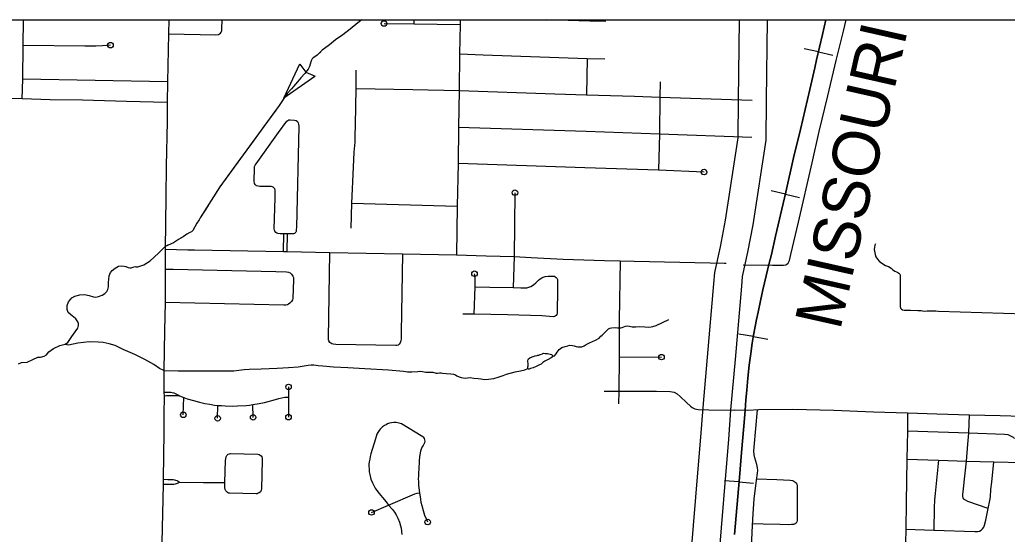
# Model space of a CAD drawing. Extents: x 670147 to 673275, y 705573 to 707613.
# Drawn here: x 671751.4 to 671930, y 706596.3 to 706689.4 of the extents above; entities that cross this region are included whole.
import ezdxf

# ---------------------------------------------------------------- set-up
doc = ezdxf.new("R2010")
doc.units = 0
for name, color, linetype in [('15', 7, 'Continuous'), ('33', 7, 'Continuous'), ('35', 7, 'Continuous'), ('40', 7, 'Continuous'), ('43', 7, 'Continuous'), ('R_NoPlot', 7, 'Continuous')]:
    doc.layers.add(name, color=color, linetype=linetype)

msp = doc.modelspace()

# ---------------------------------------------------------------- linework, layer by layer
at = {"layer": '15'}
for points in [[(671881.3, 706668.03), (671881.36, 706674.84), (671881.54, 706689.36)], [(671886.54, 706689.36), (671886.36, 706674.78), (671886.29, 706667.62)], [(671872.81, 706592.8), (671874.09, 706608.19), (671874.56, 706613.87), (671874.96, 706619.24), (671875.76, 706628.34), (671876.92, 706641.62), (671877.08, 706643.69), (671878.11, 706648.33), (671879.02, 706653.1), (671881.3, 706668.03)], [(671886.29, 706667.62), (671883.94, 706652.26), (671883.01, 706647.33), (671882.04, 706642.95), (671881.9, 706641.2), (671880.74, 706627.91), (671879.95, 706618.84), (671879.55, 706613.48), (671879.07, 706607.77), (671877.8, 706592.39)]]:
    msp.add_lwpolyline(points, dxfattribs=at)
at = {"layer": '33'}
for points in [[(671751.86, 706675.07), (671751.98, 706678.6), (671752.06, 706684.72), (671752.09, 706689.36)], [(671778.36, 706689.36), (671778.33, 706686.82), (671778.17, 706678.14), (671778.08, 706674.37), (671778.07, 706670.98), (671777.92, 706662.91), (671777.87, 706657.34), (671777.71, 706647.9), (671777.75, 706644.28), (671777.75, 706638.26), (671777.62, 706633.11), (671777.5, 706625.93), (671777.5, 706622.05), (671777.52, 706621.31), (671777.51, 706618.04), (671777.5, 706614.82), (671777.35, 706606.28), (671777.33, 706605.34), (671777.13, 706594.83)], [(671778.33, 706686.82), (671786.91, 706686.62), (671787.39, 706686.71), (671787.73, 706686.93), (671787.87, 706687.1), (671787.96, 706687.36), (671787.99, 706687.7), (671788.02, 706689.36)], [(671822.75, 706688.63), (671822.75, 706689.36)], [(671831.07, 706689.36), (671831.05, 706688.5), (671830.96, 706683.18), (671830.85, 706676.58), (671830.76, 706669.95), (671830.67, 706663.36), (671830.54, 706655.67), (671830.38, 706646.87)], [(671857.37, 706689.02), (671854.48, 706689.1), (671846.6, 706689.36)], [(671854.48, 706689.36), (671854.48, 706689.1)], [(671900.33, 706687.31), (671900.81, 706689.36)], [(671817.29, 706688.68), (671822.75, 706688.63), (671831.05, 706688.5)], [(671882.21, 706645.06), (671887.52, 706644.99), (671888.93, 706644.98), (671889.53, 706644.99), (671889.95, 706645.05), (671890.13, 706645.15), (671890.33, 706645.38), (671890.58, 706645.84), (671890.84, 706646.92), (671892.21, 706652.75), (671894.68, 706663.47), (671895.97, 706669.16), (671897.51, 706675.62), (671899.01, 706682.02), (671900.33, 706687.31)], [(671767.84, 706684.76), (671766.41, 706684.65), (671765.2, 706684.56), (671764.45, 706684.56), (671763.21, 706684.56), (671752.06, 706684.72)], [(671830.96, 706683.18), (671835.21, 706683.04), (671854.01, 706682.37), (671857.23, 706682.31)], [(671854.01, 706682.37), (671853.87, 706675.77)], [(671811.33, 706651.66), (671811.49, 706656.18), (671811.75, 706662.71), (671811.92, 706665.41), (671812.05, 706667.22), (671812.06, 706668.37), (671812.14, 706670.37), (671812.25, 706676.92), (671812.26, 706680.25)], [(671778.17, 706678.14), (671751.98, 706678.6)], [(671812.25, 706676.92), (671822.48, 706676.77), (671830.85, 706676.58)], [(671830.85, 706676.58), (671848.19, 706675.98), (671853.87, 706675.77), (671862.56, 706675.52), (671867.16, 706675.36), (671883.86, 706674.81)], [(671867.19, 706678.14), (671867.16, 706675.36), (671867.08, 706668.76), (671866.89, 706662.14)], [(671778.08, 706674.37), (671770.72, 706674.56), (671762.79, 706674.81), (671756.96, 706674.9), (671751.86, 706675.07), (671747.69, 706675.11), (671746.42, 706675.14), (671742.28, 706675.22), (671733.94, 706675.42), (671725.56, 706675.57), (671722.68, 706675.63), (671718.93, 706675.66), (671714.77, 706675.79), (671699.06, 706676.14)], [(671799.85, 706650.63), (671799.16, 706650.65), (671798.5, 706650.68), (671798.08, 706650.71), (671797.91, 706650.79), (671797.73, 706650.91), (671797.55, 706651.12), (671797.46, 706651.32), (671797.45, 706651.56), (671797.6, 706657.18), (671797.6, 706658.53), (671797.53, 706658.77), (671797.38, 706658.97), (671797.26, 706659.07), (671797.13, 706659.13), (671796.9, 706659.2), (671794.81, 706659.23), (671794.51, 706659.25), (671794.25, 706659.35), (671794.06, 706659.52), (671793.88, 706659.73), (671793.85, 706659.87), (671793.83, 706660.12), (671793.86, 706662.58), (671793.89, 706662.83), (671793.98, 706663.07), (671794.18, 706663.33), (671798.22, 706668.99), (671799.71, 706671), (671799.9, 706671.17), (671800.07, 706671.24), (671800.29, 706671.25), (671801.1, 706671.21), (671801.38, 706671.17), (671801.63, 706670.97), (671801.78, 706670.74), (671801.85, 706670.5), (671801.87, 706670.07), (671801.46, 706651.87), (671801.43, 706651.41), (671801.4, 706651.09), (671801.32, 706650.94), (671801.22, 706650.83), (671801.08, 706650.74), (671800.92, 706650.68), (671800.69, 706650.64), (671800.29, 706650.63), (671799.85, 706650.63)], [(671830.76, 706669.95), (671853.83, 706669.19), (671867.08, 706668.76), (671883.8, 706668.16)], [(671875.14, 706661.82), (671866.89, 706662.14), (671853.6, 706662.61), (671830.67, 706663.36)], [(671840.95, 706658.09), (671840.81, 706646.55)], [(671811.49, 706656.18), (671830.54, 706655.67)], [(671799.09, 706647.46), (671799.16, 706650.65)], [(671799.76, 706647.46), (671799.85, 706650.63)], [(671777.71, 706647.9), (671781.81, 706647.78), (671783.01, 706647.74), (671799.09, 706647.46), (671799.76, 706647.46), (671807.52, 706647.3), (671820.6, 706647.07), (671830.38, 706646.87), (671835.78, 706646.7), (671840.81, 706646.55), (671843.88, 706646.4), (671849.66, 706646.09), (671857.12, 706645.83), (671860, 706645.78), (671862.52, 706645.72), (671876.27, 706645.44), (671878.87, 706645.34), (671879.12, 706645.33)], [(671906.17, 706648.85), (671906.02, 706648.63), (671905.93, 706648.24), (671905.92, 706647.83), (671906.07, 706646.95), (671906.23, 706646.47), (671906.48, 706646.08), (671906.8, 706645.69), (671907.3, 706645.33), (671907.96, 706644.96), (671908.52, 706644.73), (671908.97, 706644.46), (671909.22, 706644.22), (671909.62, 706643.89), (671909.92, 706643.76), (671910.18, 706643.68), (671910.34, 706643.56), (671910.53, 706643.39), (671910.61, 706643.25), (671910.6, 706642.91), (671910.62, 706641.62), (671910.62, 706639.54), (671910.6, 706637.55), (671910.69, 706637.23), (671910.83, 706637.03), (671911.03, 706636.92), (671911.3, 706636.86), (671911.58, 706636.85), (671912.44, 706636.86), (671913.78, 706636.82), (671914.39, 706636.79), (671914.65, 706636.74), (671915, 706636.7), (671915.48, 706636.74), (671916.17, 706636.74), (671917.03, 706636.74), (671917.52, 706636.7), (671933.17, 706636.2)], [(671820.6, 706647.07), (671820.38, 706632.84), (671820.38, 706631.67), (671820.35, 706631.34), (671820.29, 706631.13), (671820.19, 706630.93), (671820.04, 706630.72), (671819.82, 706630.55), (671819.62, 706630.48), (671819.4, 706630.48), (671808.55, 706630.66), (671808.11, 706630.7), (671807.86, 706630.75), (671807.67, 706630.87), (671807.5, 706631.03), (671807.34, 706631.3), (671807.27, 706631.48), (671807.23, 706631.76), (671807.52, 706647.3)], [(671840.81, 706646.55), (671840.64, 706640.98)], [(671777.75, 706644.28), (671779.17, 706644.29), (671797.72, 706643.83), (671799.67, 706643.79), (671799.99, 706643.73), (671800.3, 706643.58), (671800.56, 706643.38), (671800.7, 706643.21), (671800.83, 706642.98), (671800.9, 706642.76), (671800.92, 706642.4), (671800.8, 706638.98), (671800.74, 706638.72), (671800.57, 706638.41), (671800.27, 706638.11), (671800.01, 706637.92), (671799.83, 706637.84), (671799.56, 706637.79), (671799.17, 706637.79), (671777.75, 706638.26)], [(671860, 706645.78), (671859.8, 706635.04)], [(671833.57, 706636.11), (671833.74, 706641.06), (671833.76, 706642.44), (671833.74, 706642.94), (671833.65, 706643.44)], [(671840.64, 706640.98), (671842.05, 706640.92), (671842.9, 706640.91), (671843.1, 706640.92), (671843.44, 706640.99), (671843.82, 706641.12), (671844.33, 706641.43), (671844.75, 706641.78), (671845.2, 706642.27), (671845.53, 706642.52), (671845.8, 706642.7), (671846.05, 706642.81), (671846.42, 706642.93), (671846.96, 706642.99), (671847.55, 706643.02), (671847.95, 706643.01), (671848.12, 706642.98), (671848.25, 706642.91), (671848.4, 706642.78), (671848.5, 706642.64), (671848.58, 706642.53), (671848.63, 706642.39), (671848.67, 706640.18), (671848.61, 706636.85), (671848.6, 706636.32), (671848.52, 706636.07), (671848.38, 706635.89), (671848.23, 706635.77), (671848.09, 706635.7), (671847.93, 706635.68), (671845.79, 706635.81), (671839.59, 706635.99)], [(671833.74, 706641.06), (671836.39, 706640.99), (671840.64, 706640.98)], [(671839.59, 706635.99), (671833.57, 706636.11), (671831.53, 706636.16)], [(671859.8, 706635.04), (671859.8, 706628.45), (671859.73, 706622.24), (671859.65, 706619.94)], [(671859.8, 706628.45), (671867.45, 706628.37)], [(671800.03, 706622.98), (671800, 706621.11), (671800.01, 706617.51)], [(671777.5, 706622.05), (671777.99, 706622.03), (671778.49, 706622.02), (671778.77, 706622.01), (671778.97, 706621.98), (671779.26, 706621.89), (671779.66, 706621.71), (671780, 706621.55), (671780.31, 706621.36), (671779.95, 706621.35), (671779.43, 706621.37), (671778.6, 706621.39), (671777.97, 706621.36), (671777.52, 706621.31)], [(671780.31, 706621.36), (671781.11, 706621.04), (671781.7, 706620.84), (671782.82, 706620.5), (671783.92, 706620.22), (671784.91, 706619.99), (671785.78, 706619.84), (671786.62, 706619.71), (671787.27, 706619.63), (671787.88, 706619.6), (671788.54, 706619.56), (671789.81, 706619.51), (671790.77, 706619.54), (671792.36, 706619.65), (671792.95, 706619.71), (671793.59, 706619.8), (671794.7, 706619.97), (671795.66, 706620.16), (671796.33, 706620.32), (671797.23, 706620.58), (671798.26, 706620.91), (671798.84, 706621.02), (671799.35, 706621.1), (671800, 706621.11)], [(671857.08, 706622.21), (671859.73, 706622.24), (671866.56, 706622.2), (671869, 706622.13), (671869.75, 706622.02), (671870.27, 706621.76), (671870.84, 706621.27), (671871.98, 706620.17), (671872.71, 706619.48), (671873.02, 706619.24), (671873.46, 706619.02), (671874.09, 706618.89), (671876.03, 706618.83), (671880.7, 706618.78)], [(671781, 706617.94), (671781.11, 706621.04)], [(671787.21, 706617.31), (671787.27, 706619.63)], [(671793.62, 706617.48), (671793.59, 706619.8)], [(671911.93, 706618.24), (671905.78, 706618.4), (671898.59, 706618.72), (671891.21, 706618.9), (671885.06, 706618.86), (671883.04, 706618.73), (671880.7, 706618.78)], [(671882.19, 706591.77), (671883.16, 706592.34), (671883.7, 706594), (671883.89, 706597.95), (671884.05, 706600.02), (671884.23, 706602.76), (671884.61, 706606.04), (671884.8, 706607.37), (671884.86, 706607.88), (671884.82, 706608.36), (671884.68, 706608.93), (671884.48, 706609.56), (671884.32, 706610.15), (671884.2, 706610.7), (671884.16, 706611.34), (671884.23, 706612.07), (671884.83, 706618.85)], [(671911.93, 706618.24), (671911.9, 706614.98), (671911.79, 706609.9), (671911.66, 706602.1), (671911.64, 706597.24), (671911.56, 706594.75)], [(671932.61, 706617.66), (671928.68, 706617.78), (671923.12, 706617.9), (671917.23, 706618.04), (671913.71, 706618.17), (671911.93, 706618.24)], [(671926.53, 706600.99), (671922.82, 706602.27), (671922.39, 706602.5), (671922.2, 706602.63), (671922.1, 706602.78), (671921.97, 706602.95), (671921.92, 706603.15), (671921.92, 706603.52), (671922.02, 706604.53), (671922.22, 706606.33), (671922.58, 706609.56), (671922.82, 706612.61), (671923.02, 706614.61), (671923.07, 706616.35), (671923.12, 706617.9)], [(671825.18, 706598.55), (671824.97, 706599.1), (671824.69, 706599.76), (671824.42, 706600.57), (671824.17, 706601.46), (671824.03, 706602.08), (671823.93, 706602.7), (671823.75, 706603.83), (671823.65, 706604.75), (671823.61, 706605.18), (671823.58, 706605.89), (671823.55, 706606.35), (671823.58, 706606.85), (671823.59, 706607.51), (671823.64, 706608.1), (671823.73, 706609.58), (671823.78, 706610.38), (671823.87, 706611.02), (671823.97, 706611.44), (671824.13, 706611.95), (671824.39, 706612.34), (671824.56, 706612.68), (671824.66, 706612.93), (671824.71, 706613.2), (671824.69, 706613.4), (671824.61, 706613.63), (671824.46, 706613.81), (671824.31, 706613.96), (671824.02, 706614.16), (671820.43, 706616.31), (671820, 706616.44), (671819.46, 706616.55), (671819.09, 706616.55), (671818.66, 706616.51), (671818.27, 706616.43), (671817.94, 706616.29), (671817.65, 706616.14), (671817.38, 706615.99), (671817.01, 706615.75), (671816.85, 706615.6), (671816.58, 706615.33), (671816.39, 706615.08), (671816.19, 706614.77), (671816, 706614.42), (671815.74, 706613.6), (671814.9, 706610.86), (671814.8, 706610.38), (671814.7, 706609.92), (671814.62, 706609.45), (671814.57, 706608.99), (671814.57, 706608.67), (671814.58, 706608.16), (671814.61, 706607.62), (671814.71, 706607.16), (671814.93, 706606.31), (671815.18, 706605.64), (671815.42, 706605.15), (671815.71, 706604.67), (671816.01, 706604.24), (671816.41, 706603.72), (671817.01, 706603.01), (671817.66, 706602.21), (671818.1, 706601.6), (671818.8, 706600.82), (671819.17, 706600.31), (671819.47, 706599.86), (671819.79, 706599.24), (671820.09, 706598.53), (671820.29, 706597.85), (671820.39, 706597.44), (671820.52, 706596.29)], [(671931.25, 706613.68), (671931.06, 706613.81), (671930.63, 706614.09), (671930.11, 706614.3), (671929.46, 706614.41), (671923.02, 706614.61), (671911.9, 706614.98)], [(671788.51, 706605.68), (671788.64, 706609.68), (671788.72, 706610.36), (671788.86, 706610.6), (671789.12, 706610.83), (671789.34, 706610.9), (671789.55, 706610.94), (671794.45, 706610.84), (671794.69, 706610.79), (671794.92, 706610.65), (671795.07, 706610.5), (671795.19, 706610.32), (671795.25, 706610.07), (671795.27, 706609.76), (671795.14, 706604.55), (671795.08, 706604.3), (671794.93, 706604.04), (671794.69, 706603.84), (671794.55, 706603.75), (671794.38, 706603.68), (671794.2, 706603.66), (671789.34, 706603.79), (671789.16, 706603.8), (671788.98, 706603.88), (671788.86, 706603.99), (671788.71, 706604.18), (671788.58, 706604.41), (671788.53, 706604.75), (671788.5, 706605.16), (671788.51, 706605.68)], [(671911.64, 706597.24), (671916.69, 706597.09), (671924.08, 706596.82), (671924.64, 706596.84), (671924.97, 706596.93), (671925.26, 706597.11), (671925.51, 706597.35), (671925.71, 706597.63), (671925.84, 706597.97), (671926.08, 706598.88), (671926.53, 706600.99), (671926.84, 706602.43), (671926.92, 706603.14), (671927.01, 706604.43), (671927.19, 706605.78), (671927.54, 706609.44)], [(671911.79, 706609.9), (671917.5, 706609.75), (671922.58, 706609.56), (671927.54, 706609.44), (671932.76, 706609.29)], [(671917.5, 706609.75), (671916.93, 706603.69), (671916.83, 706602.57), (671916.75, 706601.13), (671916.69, 706597.09)], [(671777.35, 706606.28), (671778.21, 706606.26), (671779.14, 706606.25), (671779.43, 706606.2), (671779.59, 706606.14), (671779.82, 706606.05), (671780.06, 706605.94), (671780.23, 706605.83), (671780.33, 706605.77), (671780.24, 706605.73), (671780.07, 706605.61), (671779.74, 706605.44), (671779.55, 706605.39), (671779.31, 706605.37), (671778.55, 706605.34), (671777.33, 706605.34)], [(671780.33, 706605.77), (671784.67, 706605.68), (671788.51, 706605.68)], [(671884.64, 706606.35), (671888.33, 706606.27), (671890.72, 706606.14), (671891.12, 706606.04), (671891.4, 706605.92), (671891.57, 706605.8), (671891.75, 706605.66), (671891.92, 706605.41), (671891.97, 706605.26), (671892, 706604.97), (671892, 706599.05), (671891.98, 706598.82), (671891.93, 706598.57), (671891.79, 706598.38), (671891.63, 706598.24), (671891.47, 706598.15), (671891.31, 706598.11), (671890.94, 706598.08), (671890.46, 706598.07), (671888.92, 706598.08), (671885.81, 706598.15), (671883.91, 706598.23)], [(671815.02, 706600.29), (671818.1, 706601.6), (671822.84, 706603.63), (671823.27, 706603.78), (671823.75, 706603.83)]]:
    msp.add_lwpolyline(points, dxfattribs=at)
for centre in [(671817.29, 706688.68), (671767.84, 706684.76), (671875.14, 706661.82), (671840.95, 706658.09), (671833.65, 706643.44), (671867.45, 706628.37), (671800.03, 706622.98), (671781, 706617.94), (671787.21, 706617.31), (671793.62, 706617.48), (671800.01, 706617.51), (671815.02, 706600.29), (671825.18, 706598.55)]:
    msp.add_circle(centre, 0.5, dxfattribs=at)
at = {"layer": '35'}
for points in [[(671751.22, 706627.13), (671751.77, 706627.37), (671752.76, 706627.48), (671753.78, 706627.93), (671754.69, 706628.38), (671755.2, 706628.38), (671755.87, 706628.55), (671756.24, 706628.8), (671756.72, 706629.31), (671757.51, 706629.91), (671758.7, 706630.47), (671759.65, 706630.72), (671760.13, 706631.04), (671760.82, 706632.08), (671761.44, 706632.96), (671761.95, 706633.61), (671762.06, 706634.09), (671762.05, 706634.43), (671761.94, 706634.74), (671761.58, 706635.29), (671761.12, 706635.65), (671760.96, 706635.76), (671760.2, 706636.43), (671760.03, 706637), (671760.03, 706637.71), (671760.22, 706638.36), (671760.86, 706639.06), (671761.41, 706639.38), (671762.28, 706639.63), (671763.16, 706639.69), (671763.97, 706639.5), (671764.75, 706639.27), (671765.17, 706639.21), (671765.68, 706639.33), (671766.34, 706639.55), (671766.8, 706639.88), (671767.16, 706640.22), (671767.36, 706640.61), (671767.46, 706641.08), (671767.45, 706641.86), (671767.54, 706642.45), (671767.59, 706643.07), (671767.84, 706643.68), (671768.11, 706644.03), (671768.69, 706644.46), (671769.31, 706644.79), (671769.86, 706644.88), (671770.29, 706644.84), (671770.64, 706644.73), (671771.03, 706644.56), (671771.31, 706644.5), (671771.56, 706644.5), (671771.92, 706644.64), (671772.26, 706644.74), (671772.4, 706644.72), (671772.76, 706644.69), (671773.86, 706645.04), (671774.98, 706645.78), (671776.52, 706647.17), (671777.71, 706648.38)], [(671847.83, 706628.52), (671848.13, 706628.63), (671848.4, 706628.94), (671848.6, 706629.28), (671848.96, 706629.74), (671849.45, 706630.1), (671850.02, 706630.3), (671850.52, 706630.43), (671850.83, 706630.5), (671851.34, 706630.46), (671851.64, 706630.38), (671852, 706630.3), (671852.32, 706630.21), (671852.67, 706630.21), (671853.04, 706630.25), (671853.46, 706630.41), (671853.82, 706630.63), (671854.46, 706630.96), (671855.51, 706631.43), (671856.18, 706631.82), (671856.51, 706632.17), (671856.71, 706632.35), (671856.95, 706632.58), (671857.3, 706632.92), (671857.88, 706633.49), (671858.11, 706633.6), (671858.42, 706633.69), (671859.18, 706633.73), (671859.51, 706633.68), (671859.8, 706633.66), (671860.08, 706633.68), (671860.35, 706633.75), (671860.95, 706633.97), (671861.33, 706634), (671861.65, 706633.98), (671862.13, 706633.84), (671862.81, 706633.85), (671863.49, 706633.9), (671864.44, 706633.86), (671865.18, 706633.81), (671865.56, 706633.85), (671865.91, 706633.9), (671866.46, 706634.08), (671868.76, 706635.16)], [(671777.5, 706625.93), (671776.71, 706626.31), (671775.66, 706627.06), (671774.05, 706627.92), (671772.21, 706628.86), (671770.1, 706629.77), (671768.67, 706630.44), (671767.58, 706630.78), (671766.49, 706631.01), (671765.59, 706631.08), (671763.98, 706631.16), (671761.95, 706630.89), (671760.26, 706630.55), (671759.99, 706630.59), (671759.65, 706630.72)], [(671845.83, 706627.22), (671845.7, 706627.12), (671845.4, 706626.99), (671844.78, 706626.67), (671844.25, 706626.46), (671843.78, 706626.33), (671843.5, 706626.2), (671843.4, 706626.2), (671843.3, 706626.25), (671843.26, 706626.32), (671843.27, 706626.51), (671843.29, 706626.62), (671843.34, 706626.77), (671843.33, 706627.09), (671843.29, 706627.72), (671843.33, 706627.91), (671843.42, 706628.08), (671843.66, 706628.25), (671844.07, 706628.43), (671844.59, 706628.59)], [(671844.59, 706628.59), (671844.97, 706628.68), (671845.11, 706628.72), (671845.29, 706628.73), (671845.53, 706628.85), (671845.91, 706628.98), (671846.01, 706629.05), (671846.14, 706629.07), (671846.43, 706629.04), (671846.85, 706629.01), (671847.33, 706628.93), (671847.59, 706628.82), (671847.7, 706628.73), (671847.8, 706628.63), (671847.83, 706628.58), (671847.83, 706628.52), (671847.76, 706628.42), (671847.51, 706628.27), (671846.94, 706627.93), (671846.39, 706627.63), (671846, 706627.38), (671845.83, 706627.22)], [(671777.5, 706625.93), (671780.07, 706625.89), (671783.02, 706625.91), (671789.29, 706625.92), (671790.12, 706625.88), (671791.05, 706626.01), (671791.99, 706626.13), (671792.89, 706626.2), (671795.07, 706626.24), (671797.95, 706626.37), (671799.99, 706626.47), (671801.75, 706626.6), (671802.88, 706626.79), (671803.59, 706626.92), (671804.11, 706626.95), (671804.57, 706626.95), (671805, 706626.93), (671805.37, 706626.87), (671806.24, 706626.82), (671808.14, 706626.64), (671810.72, 706626.52), (671813.8, 706626.34), (671818.09, 706626.08), (671820.78, 706625.85), (671821.55, 706625.72), (671822.3, 706625.72), (671823.39, 706625.77), (671823.95, 706625.8), (671824.87, 706625.67), (671825.46, 706625.67), (671826.12, 706625.62), (671826.69, 706625.48), (671826.96, 706625.45), (671827.31, 706625.52), (671827.59, 706625.53), (671827.84, 706625.48), (671828.54, 706625.4), (671829.34, 706625.35), (671829.83, 706625.27), (671830.21, 706625.17), (671830.45, 706625), (671830.85, 706624.78), (671831.26, 706624.67), (671831.61, 706624.62), (671831.96, 706624.58), (671832.37, 706624.62), (671832.84, 706624.67), (671833.54, 706624.57), (671834.29, 706624.48), (671834.79, 706624.42), (671835.51, 706624.35), (671836.18, 706624.37), (671837.11, 706624.5), (671837.9, 706624.72), (671838.85, 706625.07), (671839.43, 706625.27), (671840.99, 706625.72), (671841.94, 706625.89), (671842.72, 706626.07), (671843.26, 706626.32)]]:
    msp.add_lwpolyline(points, dxfattribs=at)
at = {"layer": '40'}
for p, q in [((671895.83, 706683.53), (671893.26, 706684.13)), ((671895.83, 706683.53), (671898.4, 706682.93)), ((671889.84, 706657.82), (671887.26, 706658.41)), ((671889.84, 706657.82), (671892.41, 706657.23)), ((671884.06, 706632.07), (671881.45, 706632.49)), ((671884.06, 706632.07), (671886.66, 706631.64)), ((671881.46, 706605.8), (671878.83, 706606.02)), ((671881.46, 706605.8), (671884.09, 706605.58))]:
    msp.add_line(p, q, dxfattribs=at)
for points in [[(671897.19, 706689.36), (671896.56, 706686.69), (671895.5, 706682.11), (671895.17, 706680.64), (671894.26, 706676.76), (671893.41, 706673.14), (671892.61, 706669.5), (671891.33, 706664.4), (671889.92, 706658.2), (671889.46, 706656.17), (671888.06, 706650.21), (671887.31, 706646.95), (671886.87, 706645.11), (671886.4, 706643.07), (671885.8, 706640.52), (671885.35, 706638.52), (671884.9, 706636.5), (671884.64, 706635.2), (671884.39, 706633.88), (671884.1, 706632.33), (671883.87, 706630.92), (671883.6, 706629.04), (671883.3, 706626.89), (671883.04, 706624.57), (671882.85, 706622.37), (671882.7, 706620.65), (671882.57, 706618.71), (671882.31, 706615.89), (671881.9, 706611.15), (671881.53, 706606.63), (671880.66, 706596.28)], [(671885.8, 706640.52), (671886.4, 706643.07), (671886.87, 706645.11), (671887.31, 706646.95), (671888.06, 706650.21), (671889.46, 706656.17), (671889.92, 706658.2), (671891.33, 706664.4), (671892.61, 706669.5), (671893.41, 706673.14), (671894.26, 706676.76), (671895.17, 706680.64), (671895.5, 706682.11), (671896.56, 706686.69), (671897.19, 706689.36)], [(671897.19, 706689.36), (671896.56, 706686.69), (671895.5, 706682.11), (671895.17, 706680.64), (671894.26, 706676.76), (671893.41, 706673.14), (671892.61, 706669.5), (671891.33, 706664.4), (671889.92, 706658.2), (671889.46, 706656.17), (671888.06, 706650.21), (671887.31, 706646.95), (671886.87, 706645.11), (671886.4, 706643.07), (671885.8, 706640.52)], [(671880.66, 706596.28), (671881.53, 706606.63), (671881.9, 706611.15), (671882.31, 706615.89), (671882.57, 706618.71), (671882.7, 706620.65), (671882.85, 706622.37), (671883.04, 706624.57), (671883.3, 706626.89), (671883.6, 706629.04), (671883.87, 706630.92), (671884.1, 706632.33), (671884.39, 706633.88), (671884.64, 706635.2), (671884.9, 706636.5), (671885.35, 706638.52), (671885.8, 706640.52)], [(671885.8, 706640.52), (671885.35, 706638.52), (671884.9, 706636.5), (671884.64, 706635.2), (671884.39, 706633.88), (671884.1, 706632.33), (671883.87, 706630.92), (671883.6, 706629.04), (671883.3, 706626.89), (671883.04, 706624.57), (671882.85, 706622.37), (671882.7, 706620.65), (671882.57, 706618.71), (671882.31, 706615.89), (671881.9, 706611.15), (671881.53, 706606.63), (671880.66, 706596.28)]]:
    msp.add_lwpolyline(points, dxfattribs=at)
at = {"layer": '43'}
for p, q in [((671799.15, 706675.2), (671802.07, 706681.41)), ((671802.04, 706681.35), (671803.13, 706679.89)), ((671804.78, 706679.12), (671799.15, 706675.2)), ((671803.15, 706679.87), (671804.83, 706679.16))]:
    msp.add_line(p, q, dxfattribs=at)
for points in [[(671813.28, 706689.36), (671812.56, 706688.8), (671811.16, 706687.68), (671809.85, 706686.62), (671808.49, 706685.7), (671807.41, 706684.83), (671806.52, 706684.15), (671806.12, 706683.84), (671805.58, 706683.29), (671805.21, 706682.96), (671804.79, 706682.68), (671804.47, 706682.49), (671804.28, 706682.27), (671804.17, 706682.08), (671804.13, 706681.91), (671803.93, 706681.33), (671803.79, 706680.88), (671803.56, 706680.41), (671803.32, 706680.11), (671802.95, 706679.64), (671802.24, 706678.85), (671801.63, 706678.14), (671800.56, 706676.87), (671799.77, 706676.02), (671799.37, 706675.42), (671799.04, 706674.93), (671798.34, 706673.87), (671787.62, 706659.13), (671784.05, 706653.53), (671783.85, 706653.19), (671783.45, 706652.61), (671782.73, 706651.24), (671782.46, 706651.01), (671782.19, 706650.9), (671781.64, 706650.57), (671780.97, 706650.12), (671780.12, 706649.64), (671779.2, 706649.06), (671777.71, 706648.38)], [(671811.84, 706688.23), (671811.16, 706687.68), (671809.85, 706686.62), (671808.49, 706685.7), (671807.41, 706684.83), (671806.52, 706684.15), (671806.12, 706683.84), (671805.63, 706683.34)], [(671803.96, 706681.42), (671803.93, 706681.33), (671803.79, 706680.88), (671803.56, 706680.41), (671803.32, 706680.11), (671802.95, 706679.64), (671802.24, 706678.85), (671801.63, 706678.14), (671800.56, 706676.87), (671799.77, 706676.02), (671799.37, 706675.42), (671799.2, 706675.16)], [(671797.7, 706672.99), (671795.37, 706669.79)], [(671795.37, 706669.79), (671793.04, 706666.59)], [(671791.49, 706664.45), (671787.62, 706659.13), (671786.9, 706658)], [(671785.48, 706655.77), (671784.05, 706653.53), (671783.85, 706653.19), (671783.45, 706652.61), (671782.73, 706651.24), (671782.46, 706651.01), (671782.19, 706650.9), (671781.64, 706650.57), (671780.97, 706650.12), (671780.52, 706649.87)], [(671778.2, 706648.61), (671777.71, 706648.38)]]:
    msp.add_lwpolyline(points, dxfattribs=at)
at = {"layer": 'R_NoPlot'}
msp.add_lwpolyline([(671149.93, 706689.36), (672221.93, 706689.36), (672221.93, 705919.71), (671149.93, 705919.71)], close=True, dxfattribs=at)

# ---------------------------------------------------------------- texts
at = {"layer": '40'}
msp.add_text('MISSOURI', height=8.448, rotation=77.3, dxfattribs=at).set_placement((671899.73, 706633.05))

doc.saveas('drawing.dxf')
